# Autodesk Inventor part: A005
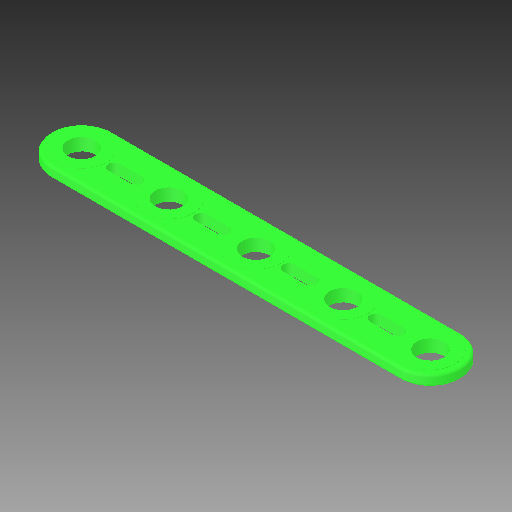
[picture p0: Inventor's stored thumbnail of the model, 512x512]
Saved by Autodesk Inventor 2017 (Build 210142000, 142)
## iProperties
Part Number: A005
Material: Générique
Document SubType Name: Modeling
Designer: ficho
Density: 1 g/cm^3
Appearance: Par défaut
Author: ficho
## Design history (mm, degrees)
feature "Solid1"
node "Solide1"
